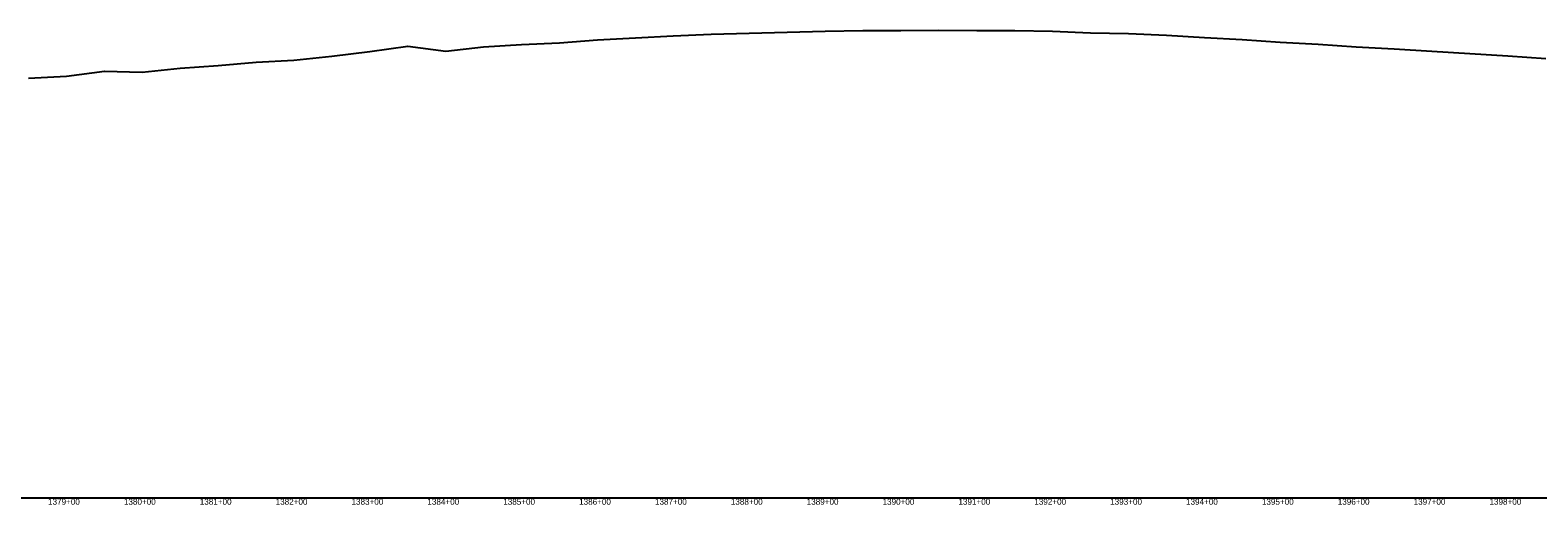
# Model space of a CAD drawing. Extents: x -3793 to 50787, y -1075 to 6138.
# Drawn here: x 23458 to 25445, y 4991 to 5616 of the extents above; entities that cross this region are included whole.
import ezdxf

# ---------------------------------------------------------------- set-up
doc = ezdxf.new("R2010")
doc.units = 0
for name, color, linetype in [('RD_DDB_Profile_EX', 7, 'Continuous'), ('RD_DDB_StaTX', 7, 'Continuous'), ('RD_GPK_Profile_Cell', 7, 'Continuous')]:
    doc.layers.add(name, color=color, linetype=linetype)

msp = doc.modelspace()

# ---------------------------------------------------------------- linework, layer by layer
at = {"layer": 'RD_DDB_Profile_EX'}
msp.add_lwpolyline([(23455.29, 5553.313015), (23505.29, 5555.776215), (23555.29, 5562.575025), (23605.29, 5561.24954), (23655.29, 5566.44775), (23705.29, 5570.05125), (23755.29, 5574.180725), (23805.29, 5577.10346), (23855.29, 5582.249295), (23905.29, 5588.28023), (23955.29, 5595.31915), (24005.29, 5588.758975), (24055.29, 5594.438605), (24105.29, 5597.547445), (24155.29, 5599.6351), (24205.29, 5603.53426), (24255.29, 5606.353035), (24305.29, 5608.922365), (24355.29, 5611.306015), (24405.29, 5612.57012), (24455.29, 5613.933645), (24505.29, 5615.264445), (24555.29, 5616.06438), (24605.29, 5615.95494), (24655.29, 5616.481825), (24705.29, 5615.887155), (24755.29, 5616.016915), (24805.29, 5615.07124), (24855.29, 5613.153675), (24905.29, 5612.14301), (24955.29, 5609.77982), (25005.29, 5606.780175), (25055.29, 5604.191325), (25105.29, 5600.763395), (25155.29, 5598.219575), (25205.29, 5594.70969), (25255.29, 5592.03304), (25305.29, 5588.99085), (25355.29, 5585.828045), (25405.29, 5582.564635), (25455.29, 5579.161235)], dxfattribs=at)
at = {"layer": 'RD_GPK_Profile_Cell'}
msp.add_line((1000, 5000), (44802.949908, 5000), dxfattribs=at)

# ---------------------------------------------------------------- texts
at = {"layer": 'RD_DDB_StaTX'}
for s, p in [('1379+00', (23481.085471, 4991)), ('1379+00', (23481.085471, 4991)), ('1380+00', (23581.085471, 4991)), ('1380+00', (23581.085471, 4991)), ('1381+00', (23681.085471, 4991)), ('1381+00', (23681.085471, 4991)), ('1382+00', (23781.085471, 4991)), ('1382+00', (23781.085471, 4991)), ('1383+00', (23881.085471, 4991)), ('1383+00', (23881.085471, 4991)), ('1384+00', (23981.085471, 4991)), ('1384+00', (23981.085471, 4991)), ('1385+00', (24081.085471, 4991)), ('1385+00', (24081.085471, 4991)), ('1386+00', (24181.085471, 4991)), ('1386+00', (24181.085471, 4991)), ('1387+00', (24281.085471, 4991)), ('1387+00', (24281.085471, 4991)), ('1388+00', (24381.085471, 4991)), ('1388+00', (24381.085471, 4991)), ('1389+00', (24481.085471, 4991)), ('1389+00', (24481.085471, 4991)), ('1390+00', (24581.085471, 4991)), ('1390+00', (24581.085471, 4991)), ('1391+00', (24681.085471, 4991)), ('1391+00', (24681.085471, 4991)), ('1392+00', (24781.085471, 4991)), ('1392+00', (24781.085471, 4991)), ('1393+00', (24881.085471, 4991)), ('1393+00', (24881.085471, 4991)), ('1394+00', (24981.085471, 4991)), ('1394+00', (24981.085471, 4991)), ('1395+00', (25081.085471, 4991)), ('1395+00', (25081.085471, 4991)), ('1396+00', (25181.085471, 4991)), ('1396+00', (25181.085471, 4991)), ('1397+00', (25281.085471, 4991)), ('1397+00', (25281.085471, 4991)), ('1398+00', (25381.085471, 4991)), ('1398+00', (25381.085471, 4991))]:
    msp.add_text(s, height=8, dxfattribs=at).set_placement(p)

doc.saveas('drawing.dxf')
